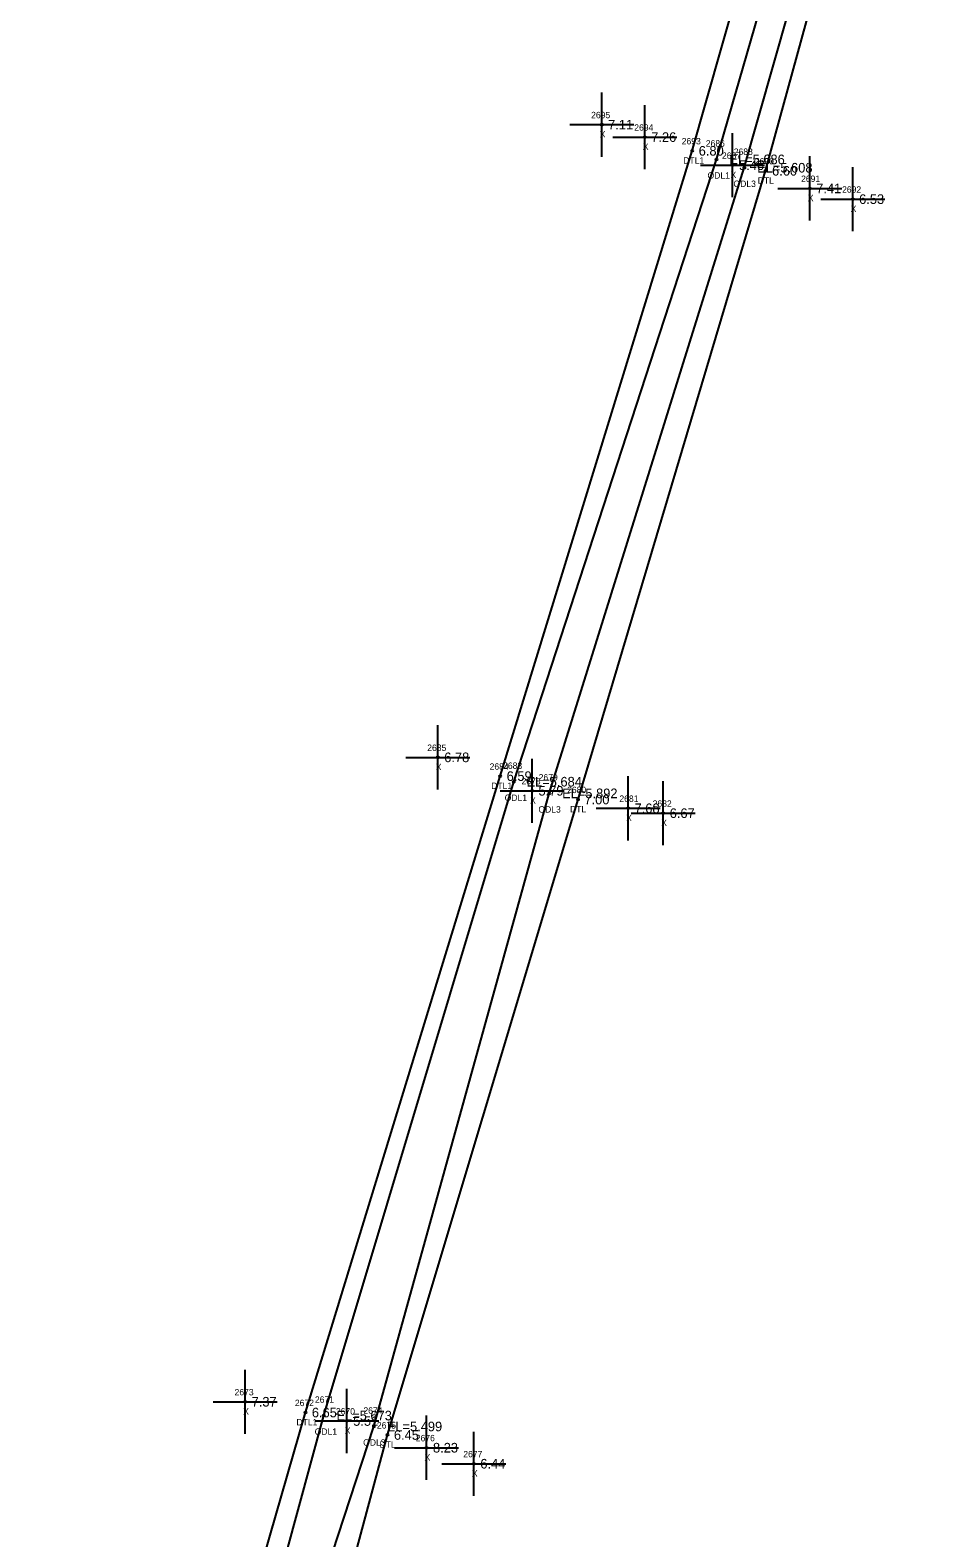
# Model space of a CAD drawing. Extents: x 2042211 to 2045853, y 303080 to 309569.
# Drawn here: x 2044716.2 to 2044857.9, y 304593.7 to 304829 of the extents above; entities that cross this region are included whole.
import ezdxf

# ---------------------------------------------------------------- set-up
doc = ezdxf.new("R2010")
doc.units = 0
for name, color, linetype in [('RD_EX_H2O', 7, 'Continuous'), ('RD_EX_H2O_txCode', 7, 'Continuous'), ('RD_EX_Misc', 7, 'Continuous'), ('RD_EX_Misc_txCode', 7, 'Continuous'), ('RD_EX_TX_H2O_ELEV', 7, 'Continuous'), ('RD_EX_TX_Misc_ELEV', 7, 'Continuous'), ('RD_SMD_Locator', 7, 'Continuous')]:
    doc.layers.add(name, color=color, linetype=linetype)

msp = doc.modelspace()

# ---------------------------------------------------------------- linework, layer by layer
at = {"layer": 'RD_EX_H2O'}
for points in [[(2044415.25, 304826.5), (2044425.66, 304808.25), (2044476.98, 304747.65), (2044539.62, 304670.39), (2044605.13, 304591.24), (2044669.3, 304516.3), (2044710.53, 304469.32), (2044713.85, 304468.76), (2044716.6, 304472.63), (2044721.53, 304481.66), (2044732.23, 304519.55), (2044759.21, 304613.29), (2044789.62, 304712.59), (2044819.6, 304810.16), (2044847.46, 304908.11)], [(2044716.81, 304455.02), (2044724.41, 304475.71), (2044736.43, 304518.58), (2044762.06, 304612.81), (2044791.72, 304711.72), (2044823.39, 304808.82), (2044851.52, 304906.14)], [(2044719.06, 304454.51), (2044726.58, 304473.3), (2044739.4, 304517.94), (2044769.91, 304611.11), (2044797.28, 304709.9), (2044827.72, 304807.52), (2044855.71, 304905.79)], [(2044719.89, 304440.12), (2044724.28, 304439.56), (2044726.76, 304444.25), (2044726.49, 304449.96), (2044727.04, 304454.87), (2044730.56, 304468.48), (2044746.81, 304516.02), (2044772.02, 304609.79), (2044801.76, 304708.94), (2044831.05, 304807.04), (2044857.93, 304905.05)]]:
    msp.add_lwpolyline(points, dxfattribs=at)
at = {"layer": 'RD_EX_Misc'}
for p, q in [((2044805.46, 304809.24), (2044805.46, 304819.24)), ((2044812.19, 304807.3), (2044812.19, 304817.3)), ((2044800.46, 304814.24), (2044810.46, 304814.24)), ((2044807.19, 304812.3), (2044817.19, 304812.3)), ((2044825.89, 304802.91), (2044825.89, 304812.91)), ((2044820.89, 304807.91), (2044830.89, 304807.91)), ((2044837.95, 304799.3), (2044837.95, 304809.3)), ((2044844.64, 304797.62), (2044844.64, 304807.62)), ((2044832.95, 304804.3), (2044842.95, 304804.3)), ((2044839.64, 304802.62), (2044849.64, 304802.62)), ((2044779.88, 304710.52), (2044779.88, 304720.52)), ((2044774.88, 304715.52), (2044784.88, 304715.52)), ((2044794.59, 304705.3), (2044794.59, 304715.3)), ((2044809.59, 304702.57), (2044809.59, 304712.57)), ((2044815.07, 304701.81), (2044815.07, 304711.81)), ((2044789.59, 304710.3), (2044799.59, 304710.3)), ((2044804.59, 304707.57), (2044814.59, 304707.57)), ((2044810.07, 304706.81), (2044820.07, 304706.81)), ((2044749.81, 304609.97), (2044749.81, 304619.97)), ((2044765.66, 304606.97), (2044765.66, 304616.97)), ((2044744.81, 304614.97), (2044754.81, 304614.97)), ((2044760.66, 304611.97), (2044770.66, 304611.97)), ((2044778.12, 304602.8), (2044778.12, 304612.8)), ((2044785.51, 304600.3), (2044785.51, 304610.3)), ((2044773.12, 304607.8), (2044783.12, 304607.8)), ((2044780.51, 304605.3), (2044790.51, 304605.3))]:
    msp.add_line(p, q, dxfattribs=at)
at = {"layer": 'RD_SMD_Locator'}
for centre in [(2044805.46, 304814.24), (2044812.19, 304812.3), (2044819.6, 304810.16), (2044823.39, 304808.82), (2044825.89, 304807.91), (2044827.72, 304807.52), (2044831.05, 304807.04), (2044837.95, 304804.3), (2044844.64, 304802.62), (2044779.88, 304715.52), (2044789.62, 304712.59), (2044791.72, 304711.72), (2044794.59, 304710.3), (2044797.28, 304709.9), (2044801.76, 304708.94), (2044809.59, 304707.57), (2044815.07, 304706.81), (2044749.81, 304614.97), (2044759.21, 304613.29), (2044762.06, 304612.81), (2044765.66, 304611.97), (2044769.91, 304611.11), (2044772.02, 304609.79), (2044778.12, 304607.8), (2044785.51, 304605.3)]:
    msp.add_circle(centre, 0.15, dxfattribs=at)

# ---------------------------------------------------------------- texts
at = {"layer": 'RD_EX_H2O_txCode'}
for s, p in [('2693', (2044817.95, 304811.16)), ('2686', (2044821.71, 304810.82)), ('2688', (2044826.07, 304809.52)), ('DTL1', (2044818.19, 304808.16)), ('2690', (2044829.36, 304808.04)), ('ODL1', (2044821.98, 304805.82)), ('ODL3', (2044826.03, 304804.52)), ('DTL', (2044829.81, 304805.04)), ('2684', (2044787.96, 304713.59)), ('2683', (2044790.07, 304713.72)), ('DTL1', (2044788.21, 304710.59)), ('2679', (2044795.62, 304711.9)), ('2680', (2044800.06, 304709.94)), ('ODL1', (2044790.31, 304708.72)), ('ODL3', (2044795.58, 304706.9)), ('DTL', (2044800.51, 304706.94)), ('2672', (2044757.56, 304614.29)), ('2671', (2044760.69, 304614.81)), ('DTL1', (2044757.8, 304611.29)), ('2674', (2044768.26, 304613.11)), ('ODL1', (2044760.65, 304609.81)), ('2675', (2044770.37, 304610.79)), ('ODL3', (2044768.22, 304608.11)), ('DTL', (2044770.78, 304607.79))]:
    msp.add_text(s, height=1, dxfattribs=at).set_placement(p)
at = {"layer": 'RD_EX_Misc_txCode'}
for s, p in [('2695', (2044803.81, 304815.24)), ('2694', (2044810.54, 304813.3)), ('X', (2044805.15, 304812.24)), ('X', (2044811.87, 304810.3)), ('2687', (2044824.23, 304808.91)), ('X', (2044825.57, 304805.91)), ('2691', (2044836.58, 304805.3)), ('X', (2044837.63, 304802.3)), ('2692', (2044842.98, 304803.62)), ('X', (2044844.32, 304800.62)), ('2685', (2044778.22, 304716.52)), ('X', (2044779.56, 304713.52)), ('2678', (2044792.94, 304711.3)), ('X', (2044794.28, 304708.3)), ('2681', (2044808.22, 304708.57)), ('2682', (2044813.41, 304707.81)), ('X', (2044809.27, 304705.57)), ('X', (2044814.75, 304704.81)), ('2673', (2044748.15, 304615.97)), ('X', (2044749.49, 304612.97)), ('2670', (2044763.97, 304612.97)), ('X', (2044765.35, 304609.97)), ('2676', (2044776.44, 304608.8)), ('2677', (2044783.85, 304606.3)), ('X', (2044777.81, 304605.8)), ('X', (2044785.19, 304603.3))]:
    msp.add_text(s, height=1, dxfattribs=at).set_placement(p)
at = {"layer": 'RD_EX_TX_H2O_ELEV'}
for s, p in [('6.80', (2044820.6, 304809.41)), ('EL=5.686', (2044825.39, 304808.07)), ('EL=5.608', (2044829.72, 304806.77)), ('6.60', (2044832.05, 304806.29)), ('6.59', (2044790.62, 304711.84)), ('EL=5.684', (2044793.72, 304710.97)), ('EL=5.892', (2044799.28, 304709.15)), ('7.00', (2044802.76, 304708.19)), ('6.65', (2044760.21, 304612.54)), ('EL=5.673', (2044764.06, 304612.06)), ('EL=5.499', (2044771.91, 304610.36)), ('6.45', (2044773.02, 304609.04))]:
    msp.add_text(s, height=1.5, dxfattribs=at).set_placement(p)
at = {"layer": 'RD_EX_TX_Misc_ELEV'}
for s, p in [('7.11', (2044806.46, 304813.49)), ('7.26', (2044813.19, 304811.55)), ('5.46', (2044826.89, 304807.16)), ('7.41', (2044838.95, 304803.55)), ('6.53', (2044845.64, 304801.87)), ('6.78', (2044780.88, 304714.77)), ('5.79', (2044795.59, 304709.55)), ('7.68', (2044810.59, 304706.82)), ('6.67', (2044816.07, 304706.06)), ('7.37', (2044750.81, 304614.22)), ('5.51', (2044766.66, 304611.22)), ('8.23', (2044779.12, 304607.05)), ('6.44', (2044786.51, 304604.55))]:
    msp.add_text(s, height=1.5, dxfattribs=at).set_placement(p)

doc.saveas('drawing.dxf')
